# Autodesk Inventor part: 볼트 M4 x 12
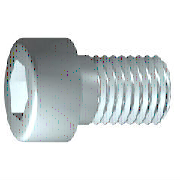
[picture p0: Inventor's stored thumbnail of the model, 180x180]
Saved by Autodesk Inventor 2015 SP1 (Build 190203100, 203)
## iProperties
IsCustomPart: 0
Created: 2012-02
Part Number: 볼트 M4 x 12
Material: 강철, 연강
Description: 6각 소켓 머리 캡 나사
Document SubType Name: Modeling
Standard: ISO 4762
Designer: mduedu
Standard Revision: Fourth edition 2004-03-01
Standards Organization: ISO
Language: ko-KR
Size Designation: M4 x 12
Categories: <MemberInstance><Categories><Category DisplayName="조임쇠" InternalName="e4da775c-781d-43d5-af7c-5136215cf5a6" Mnemonic="FSTN"><Category DisplayName="볼트" InternalN
Density: 7.75 g/cm^3
Appearance: 강철
Author: mduedu
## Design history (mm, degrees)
sketch "스케치1"
  geometry: L1 (-1, 0)-(12, 0); L2 (12, 0)-(12, 2); L3 (12, 2)-(1.75, 2); L4 (1.75, 2)-(1.32, 2); L5 (1.32, 2)-(0, 2); L6 (0, 2)-(0, 3.5); L7 (0, 3.5)-(-4, 3.5); L8 (-4, 3.5)-(-4, 1.732); L9 (-4, 1.732)-(-2, 1.732); L10 (-2, 1.732)-(-1, 0); L11 (-7.2, 0)-(15.2, 0) reference; L12 (0, -0.7)-(0, 4.2) reference; L13 (1.75, 2)-(0, 2)
  constraints: 22 end point, 6 parallel, 2 collinear, 2 perpendicular, 1 horizontal, 1 point on line
  dimensions: "d1" = 10.25 distance from line of L3.end L2 (= GEL); "d2" = 0.42952 distance of L4.end L3.end (computed from GAL); "d3" = 4 distance between parallel lines of L8 L6 (= KOH); "d4" = 2 distance of L8.end L9.end (= INTI); "d5" = 60 deg angle of L10 L1; "d6" = 4 diameter of L3 L1 (= GD); "d7" = 4 diameter of L5 L1 (= BDM); "d8" = 3.4641 diameter of L9 L1 (= 1.1547 x SW); "d9" = 7 diameter of L7 L1 (= KOD); "d26" = 12 distance between parallel lines of L12 L2 (= NLG)
revolve "본체" sketch "스케치1" stored, may be unused: angle "d10" = 90 deg
sketch "스케치2"
  geometry: L1 (0, -4.9)-(0, 4.9) reference; L2 (-4.9, 0)-(4.9, 0) reference; L3 (1.732, 0)-(0.866, -1.5); L4 (0.866, -1.5)-(-0.866, -1.5); L5 (-0.866, -1.5)-(-1.732, 0); L6 (-1.732, 0)-(-0.866, 1.5); L7 (-0.866, 1.5)-(0.866, 1.5); L8 (0.866, 1.5)-(1.732, 0); 2 further points
  constraints: 12 end point, 1 coincident, 1 horizontal alignment, 1 point on line, 12 other
extrude "슬롯" join sketch "스케치2" stored distance "d11" = 10; taper "d12" = 0 deg
workplane "Work Plane1"
fillet "Fillet2" dims "d30" = 0.1 (= R)
body "Solid1"
fillet "모깎기1" dims "d17" = 0.4 (= RR)
feature "스레드" dims "d13" = 10.25 (= GEL), "d14" = 0
chamfer "모따기1" distance "d15" = 0.42941 (= -0.5 x SPD + 0.5 x GD); stored, may be unused: second distance "d16" = 0.42941 (= GUL), angle "d27" = 45 deg
other parameters: "GD" = 4 [user parameter; used in 2 equation terms], "NLG" = 12 [user parameter; used in 1 equation term], "GEL" = 10.25 [user parameter; used in 2 equation terms], "KOD" = 7 [user parameter; used in 1 equation term], "KOH" = 4 [user parameter; used in 1 equation term], "INTI" = 2 [user parameter; used in 1 equation term], "GAL" = 0.42941 (= 0.61345 x PTC) [user parameter; used in 1 equation term], "GUL" = 0.42941 (= 0.61345 x PTC) [user parameter; used in 1 equation term], "BDM" = 4 (= NND) [user parameter; used in 1 equation term], "SW" = 3 [user parameter; used in 2 equation terms], "RR" = 0.4 [user parameter; used in 1 equation term], "SPD" = 3.14117 (= NND - 1.2269 x PTC) [user parameter; used in 1 equation term], "d19" = 0, "d28" = 0, "d29" = 0, "R" = 0.1 [user parameter; used in 1 equation term], "TOA" = 30 deg [user parameter], "GD1" = 3.14117 (= THREADDIA - 1.2269 x PTC) [user parameter], "THREADDIA" = 4 [user parameter; used in 1 equation term], "FAWI" = 45 deg [user parameter], "TPU" = 14.28571 (computed from PTC) [user parameter], "PTC" = 0.7 [user parameter; used in 5 equation terms], "NND" = 4 [user parameter; used in 2 equation terms], "E0" = 3.465 (= 1.155 x SW) [user parameter]
